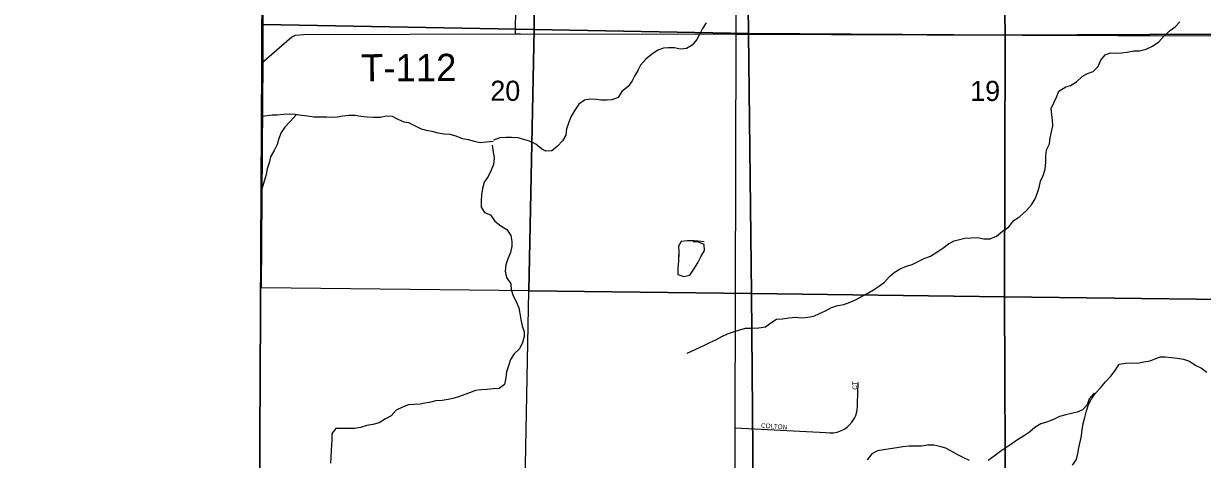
# Model space of a CAD drawing. Extents: x 1985906 to 2277390, y 930619 to 1324581.
# Drawn here: x 2110785 to 2123724, y 1169867 to 1174658 of the extents above; entities that cross this region are included whole.
import ezdxf

# ---------------------------------------------------------------- set-up
doc = ezdxf.new("R2010")
doc.units = 0
for name, color, linetype in [('GM_X_Adjacent_County', 7, 'Continuous'), ('GM_X_County', 7, 'Continuous'), ('GM_X_County_Road', 7, 'Continuous'), ('GM_X_Minor_Lake', 7, 'Continuous'), ('GM_X_Minor_River', 7, 'Continuous'), ('GM_X_Section', 7, 'Continuous'), ('GM_X_Section_Text', 7, 'Continuous'), ('GM_X_Township', 7, 'Continuous'), ('GM_X_Township_Road', 7, 'Continuous'), ('GM_X_Township_Road_Text', 7, 'Continuous'), ('GM_X_Township_Subdivision', 7, 'Continuous'), ('GM_X_Township_Subdivision_Text', 7, 'Continuous')]:
    doc.layers.add(name, color=color, linetype=linetype)

msp = doc.modelspace()

# ---------------------------------------------------------------- linework, layer by layer
at = {"layer": 'GM_X_Adjacent_County'}
msp.add_lwpolyline([(2139522, 1198874), (2139549, 1193677), (2134076, 1193549), (2129443, 1193493), (2126053, 1193488), (2117908, 1193445), (2113523, 1193411), (2113466, 1188070), (2113428, 1184374), (2113417, 1179845), (2113408, 1176168), (2113399, 1174227), (2113372, 1168723), (2113358, 1166008), (2106159, 1165987)], dxfattribs=at)
at = {"layer": 'GM_X_County'}
msp.add_lwpolyline([(2151107, 1193913), (2145028, 1193801), (2144321, 1193787), (2140582, 1193696), (2139549, 1193677), (2134076, 1193549), (2129443, 1193493), (2126053, 1193488), (2117908, 1193445), (2113523, 1193411), (2113466, 1188070), (2113428, 1184374), (2113417, 1179845), (2113408, 1176168), (2113399, 1174227), (2113372, 1168723)], dxfattribs=at)
at = {"layer": 'GM_X_County_Road'}
msp.add_lwpolyline([(2118561, 1166048), (2118587, 1166048), (2118621, 1166113), (2118623, 1166175), (2118626, 1166518), (2118591, 1169053), (2118594, 1170214), (2118606, 1174543), (2118609, 1176009), (2118650, 1179910)], dxfattribs=at)
at = {"layer": 'GM_X_Minor_Lake'}
for points in [[(2117978, 1172144), (2117974, 1172048), (2117965, 1171973), (2117967, 1171901), (2118033, 1171877), (2118098, 1171893), (2118141, 1171960), (2118187, 1172028), (2118219, 1172093), (2118259, 1172165), (2118255, 1172231), (2118192, 1172257), (2118138, 1172269)], [(2117974, 1172120), (2117974, 1172048), (2117965, 1171973), (2117967, 1171901), (2118033, 1171877), (2118098, 1171893), (2118141, 1171960), (2118187, 1172028), (2118219, 1172093), (2118259, 1172165), (2118255, 1172231), (2118192, 1172257), (2118136, 1172261)], [(2118138, 1172269), (2118072, 1172269), (2118004, 1172264), (2117972, 1172212), (2117978, 1172144)], [(2118254, 1172259), (2118192, 1172265), (2118140, 1172269), (2118072, 1172269), (2118004, 1172264), (2117972, 1172212), (2117978, 1172144)]]:
    msp.add_lwpolyline(points, dxfattribs=at)
at = {"layer": 'GM_X_Minor_River'}
for points in [[(2118276, 1174665), (2118238, 1174603), (2118210, 1174553), (2118176, 1174484), (2118124, 1174422), (2118062, 1174384), (2117996, 1174377), (2117928, 1174391), (2117862, 1174391), (2117809, 1174387), (2117745, 1174364), (2117677, 1174318), (2117615, 1174268), (2117557, 1174201), (2117530, 1174151), (2117490, 1174080), (2117464, 1174028), (2117420, 1173966), (2117352, 1173911), (2117310, 1173845), (2117242, 1173818), (2117192, 1173816), (2117122, 1173816), (2117072, 1173822)], [(2118068, 1171036), (2118204, 1171099), (2118267, 1171129), (2118317, 1171153), (2118383, 1171183), (2118448, 1171219), (2118510, 1171248), (2118578, 1171270), (2118645, 1171292), (2118709, 1171310), (2118781, 1171311), (2118855, 1171313), (2118928, 1171324), (2118988, 1171370), (2119050, 1171408), (2119116, 1171412), (2119185, 1171425), (2119257, 1171431), (2119331, 1171425), (2119393, 1171430), (2119460, 1171444), (2119522, 1171470), (2119588, 1171502), (2119653, 1171539), (2119721, 1171561), (2119789, 1171571), (2119857, 1171597), (2119922, 1171626), (2119988, 1171662), (2120052, 1171694), (2120115, 1171732), (2120179, 1171774), (2120234, 1171817), (2120290, 1171877), (2120342, 1171921), (2120407, 1171961), (2120475, 1171991), (2120539, 1172011), (2120610, 1172046), (2120678, 1172078), (2120740, 1172102), (2120809, 1172146), (2120873, 1172188), (2120936, 1172236), (2120998, 1172269), (2121058, 1172283), (2121118, 1172299), (2121187, 1172304), (2121255, 1172306), (2121323, 1172292), (2121393, 1172291), (2121463, 1172323), (2121530, 1172377), (2121598, 1172425), (2121655, 1172495), (2121721, 1172539), (2121794, 1172602), (2121848, 1172664), (2121887, 1172731), (2121909, 1172791), (2121931, 1172855), (2121948, 1172925), (2121976, 1172989), (2121997, 1173057), (2122005, 1173134), (2122005, 1173198), (2122014, 1173270), (2122044, 1173338), (2122052, 1173403), (2122067, 1173467), (2122083, 1173533), (2122077, 1173599), (2122070, 1173654), (2122062, 1173724), (2122094, 1173788), (2122123, 1173850), (2122149, 1173916), (2122226, 1173962), (2122276, 1173976), (2122342, 1174018), (2122403, 1174078), (2122463, 1174111), (2122525, 1174131), (2122578, 1174187), (2122608, 1174255), (2122657, 1174315), (2122719, 1174337), (2122785, 1174333), (2122835, 1174336), (2122899, 1174344), (2122970, 1174358), (2123032, 1174359), (2123106, 1174377), (2123177, 1174411), (2123247, 1174457), (2123305, 1174523), (2123374, 1174585), (2123424, 1174621), (2123477, 1174676)], [(2117072, 1173822), (2117001, 1173826), (2116941, 1173815), (2116879, 1173773), (2116835, 1173705), (2116793, 1173634), (2116766, 1173564), (2116744, 1173501), (2116738, 1173433), (2116702, 1173371), (2116644, 1173312), (2116582, 1173260), (2116518, 1173254), (2116468, 1173282), (2116406, 1173332), (2116337, 1173367), (2116287, 1173379), (2116213, 1173401), (2116140, 1173405), (2116078, 1173407), (2116014, 1173401), (2115944, 1173378)], [(2113781, 1173657), (2113712, 1173582), (2113652, 1173521), (2113614, 1173461), (2113586, 1173396), (2113568, 1173328), (2113534, 1173262), (2113497, 1173195), (2113479, 1173127), (2113459, 1173061), (2113447, 1172998), (2113395, 1172827)], [(2115938, 1173362), (2115866, 1173356), (2115797, 1173348), (2115733, 1173363), (2115667, 1173379), (2115601, 1173391), (2115532, 1173419), (2115468, 1173437), (2115402, 1173443), (2115335, 1173454), (2115271, 1173472), (2115221, 1173478), (2115153, 1173496), (2115012, 1173566), (2114962, 1173574), (2114897, 1173604), (2114835, 1173638), (2114767, 1173641), (2114699, 1173627), (2114626, 1173625), (2114556, 1173629), (2114488, 1173638), (2114424, 1173646), (2114355, 1173648), (2114289, 1173642), (2114227, 1173631), (2114163, 1173627), (2114113, 1173629), (2114040, 1173631), (2113970, 1173631), (2113902, 1173640), (2113834, 1173648), (2113765, 1173660), (2113701, 1173664), (2113637, 1173660), (2113569, 1173653), (2113515, 1173651), (2113399, 1173637)], [(2115930, 1173320), (2115938, 1173248), (2115949, 1173179), (2115943, 1173109), (2115919, 1173047), (2115885, 1172976), (2115842, 1172916), (2115822, 1172844), (2115812, 1172775), (2115808, 1172709), (2115807, 1172641), (2115843, 1172583), (2115909, 1172555), (2115958, 1172487), (2116024, 1172435), (2116089, 1172393), (2116133, 1172330), (2116144, 1172262), (2116146, 1172212), (2116128, 1172142), (2116102, 1172071), (2116078, 1172007), (2116071, 1171935), (2116087, 1171866), (2116134, 1171798), (2116138, 1171734), (2116158, 1171666), (2116193, 1171604), (2116221, 1171535), (2116233, 1171471), (2116244, 1171407), (2116258, 1171337), (2116278, 1171269), (2116281, 1171218), (2116263, 1171152), (2116229, 1171082), (2116169, 1171027), (2116131, 1170967), (2116106, 1170898), (2116084, 1170830), (2116078, 1170764), (2116062, 1170693), (2116004, 1170647), (2115940, 1170643), (2115872, 1170637), (2115806, 1170634), (2115744, 1170624), (2115680, 1170600), (2115547, 1170551), (2115497, 1170537), (2115447, 1170527), (2115381, 1170516), (2115309, 1170510), (2115239, 1170494), (2115188, 1170486), (2115138, 1170475), (2115070, 1170473), (2115010, 1170467), (2114946, 1170443), (2114876, 1170410), (2114820, 1170348), (2114756, 1170315), (2114688, 1170269), (2114620, 1170251), (2114551, 1170240), (2114483, 1170220), (2114419, 1170206), (2114347, 1170206), (2114281, 1170207), (2114212, 1170209), (2114169, 1170151), (2114169, 1170080), (2114165, 1170030), (2114161, 1169966), (2114156, 1169894), (2114154, 1169825)], [(2122297, 1169804), (2122340, 1169868), (2122356, 1169932), (2122366, 1169996), (2122383, 1170060), (2122395, 1170127), (2122404, 1170193), (2122416, 1170263), (2122432, 1170329), (2122453, 1170401), (2122475, 1170470), (2122508, 1170534), (2122550, 1170596), (2122604, 1170654), (2122659, 1170720), (2122719, 1170784), (2122768, 1170846), (2122810, 1170914), (2122880, 1170925), (2122945, 1170929), (2123013, 1170925), (2123081, 1170940), (2123149, 1170952), (2123214, 1170976), (2123264, 1170994), (2123316, 1170997), (2123386, 1170989), (2123452, 1170981), (2123516, 1170968), (2123583, 1170948), (2123651, 1170901), (2123713, 1170871), (2123772, 1170826)], [(2122534, 1170595), (2122480, 1170533), (2122458, 1170466), (2122408, 1170414), (2122348, 1170388), (2122288, 1170371), (2122224, 1170359), (2122154, 1170339), (2122088, 1170306), (2122014, 1170276), (2121950, 1170258), (2121886, 1170219), (2121826, 1170169), (2121760, 1170124), (2121694, 1170084), (2121632, 1170040), (2121566, 1169995), (2121501, 1169953), (2121437, 1169904), (2121372, 1169856)], [(2121167, 1169855), (2121104, 1169885), (2121040, 1169919), (2120980, 1169953), (2120909, 1169991), (2120843, 1170009), (2120775, 1170025), (2120707, 1170026), (2120642, 1170014), (2120504, 1170014), (2120434, 1170007), (2120368, 1169997), (2120295, 1169985), (2120227, 1169973), (2120159, 1169962), (2120097, 1169930), (2120043, 1169864)]]:
    msp.add_lwpolyline(points, dxfattribs=at)
at = {"layer": 'GM_X_Section'}
for points in [[(2113429, 1177211), (2116382, 1177205), (2116391, 1174593), (2113416, 1174646), (2113428, 1176982)], [(2116382, 1177205), (2118709, 1177200), (2118741, 1174548), (2116391, 1174593)], [(2118709, 1177200), (2121518, 1177192), (2121558, 1174531), (2118741, 1174548)], [(2121518, 1177192), (2123921, 1177185), (2123940, 1174541), (2121558, 1174531)], [(2113416, 1174646), (2116391, 1174593), (2116330, 1171719), (2113397, 1171754), (2113416, 1174256)], [(2116391, 1174593), (2118741, 1174548), (2118775, 1171690), (2116330, 1171719)], [(2118741, 1174548), (2121558, 1174531), (2121550, 1171656), (2118775, 1171690)], [(2121558, 1174531), (2123940, 1174541), (2123960, 1171627), (2121550, 1171656)], [(2116330, 1171719), (2118775, 1171690), (2118798, 1169109), (2116281, 1169043)], [(2118775, 1171690), (2121550, 1171656), (2121561, 1169070), (2118798, 1169109)], [(2121550, 1171656), (2123960, 1171627), (2124015, 1169066), (2121561, 1169070)]]:
    msp.add_lwpolyline(points, close=True, dxfattribs=at)
at = {"layer": 'GM_X_Township'}
msp.add_lwpolyline([(2113372, 1168723), (2113399, 1174227), (2113408, 1176168), (2113417, 1179845), (2113428, 1184374), (2113466, 1188070), (2113523, 1193411), (2117908, 1193445), (2126053, 1193488)], dxfattribs=at)
at = {"layer": 'GM_X_Township_Road'}
for points in [[(2116186, 1174546), (2116248, 1179904)], [(2113399, 1174227), (2113728, 1174514), (2113768, 1174532), (2113862, 1174539), (2116186, 1174546), (2116240, 1174546), (2118606, 1174543)], [(2118606, 1174543), (2123847, 1174524), (2127401, 1174508), (2127513, 1174507)]]:
    msp.add_lwpolyline(points, dxfattribs=at)
at = {"layer": 'GM_X_Township_Subdivision'}
msp.add_lwpolyline([(2118594, 1170214), (2119592, 1170162), (2119636, 1170159), (2119675, 1170161), (2119716, 1170169), (2119762, 1170186), (2119798, 1170205), (2119824, 1170224), (2119847, 1170243), (2119877, 1170277), (2119892, 1170300), (2119905, 1170323), (2119918, 1170352), (2119929, 1170389), (2119935, 1170417), (2119937, 1170444), (2119937, 1170483), (2119945, 1170712)], dxfattribs=at)

# ---------------------------------------------------------------- texts
at = {"layer": 'GM_X_Section_Text'}
for s, p in [('20', (2115908, 1173809)), ('19', (2121175, 1173807))]:
    msp.add_text(s, height=221, rotation=0, dxfattribs=at).set_placement(p)
at = {"layer": 'GM_X_Township_Road_Text'}
msp.add_text('T-112', height=300, rotation=0.2807, dxfattribs=at).set_placement((2114489, 1174021))
at = {"layer": 'GM_X_Township_Subdivision_Text'}
for s, rotation, p in [('CT', 90, (2119933, 1170634)), ('COLTON', 355.9166, (2118878, 1170217))]:
    msp.add_text(s, height=50, rotation=rotation, dxfattribs=at).set_placement(p)

doc.saveas('drawing.dxf')
